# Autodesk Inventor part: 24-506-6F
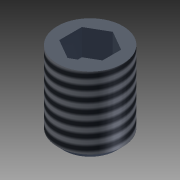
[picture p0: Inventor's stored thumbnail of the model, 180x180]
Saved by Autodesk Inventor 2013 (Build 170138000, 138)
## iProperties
Created: 2004-11
Part Number: 24-506-6F
Material: Stahl (hohe Festigk., niedr. Legier.)
Description: Set Screw, Flat Point, M6x6
Document SubType Name: Modeling
Designer: Autodesk, Inc.
Manufacturer: Standard
Standards Organization: Custom
Vendor: PARKER IPS
Catalog Web Link: http://www.parker.com/ead/cm1.asp?cmid=809
Mass: 0.787047 g
Surface Area: 1.49376 cm^2
Volume: 0.100389 cm^3
Density: 7.84 g/cm^3
CAGE: 1LJX3
Dept. ID: Product Design
Description #2: ---
Finish #1: ---
Finish #2: ---
Material ID: ---
Project Number: ---
Author: Autodesk, Inc.
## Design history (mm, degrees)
derived "24-5XX-YY Setscrews.ipt"
body "Solid1"
tag "TaggingFeature2"
feature "Solid1::24-5XX-YY Setscrews.ipt" dims "ScaleForDerivedMember" = 10
